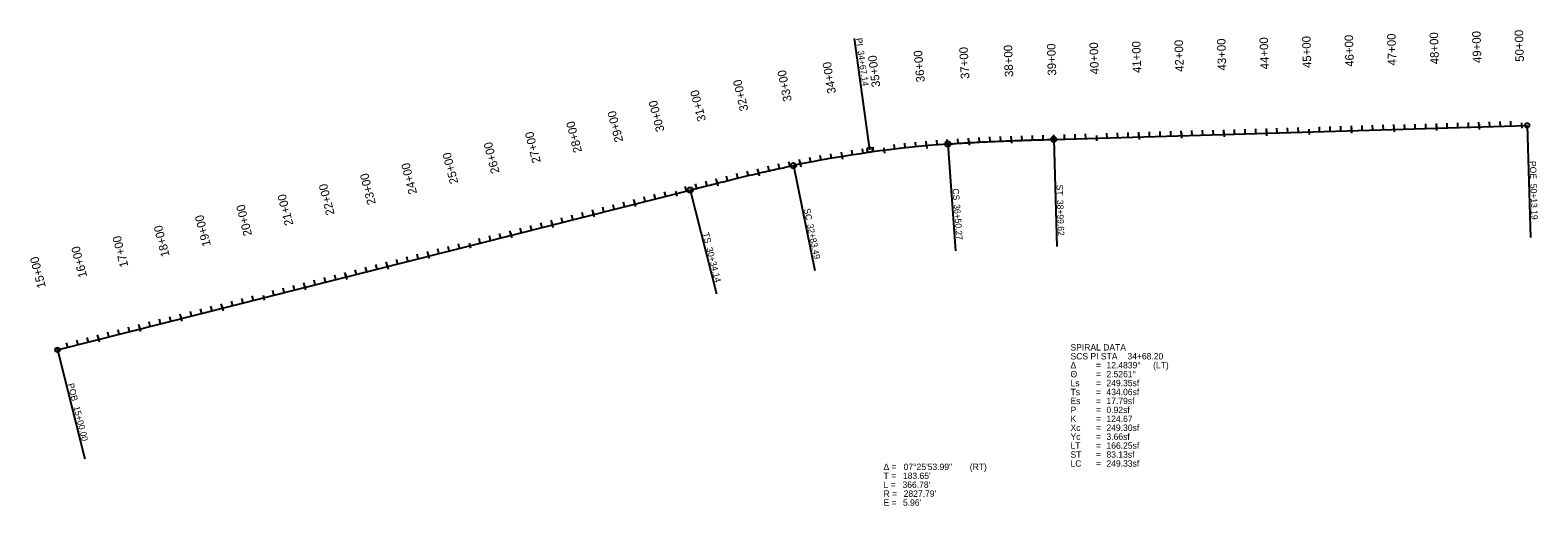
# Model space of a CAD drawing. Extents: x 21446765 to 21450310, y 8416157 to 8417275.
import ezdxf

# ---------------------------------------------------------------- set-up
doc = ezdxf.new("R2010")
doc.units = 0
for name, color, linetype in [('Alignment', 7, 'Continuous'), ('Default', 7, 'Continuous'), ('TextAlignment', 7, 'Continuous'), ('TextAlignmentLrg', 7, 'Continuous'), ('TextAlignmentSml', 7, 'Continuous')]:
    doc.layers.add(name, color=color, linetype=linetype)

msp = doc.modelspace()

# ---------------------------------------------------------------- linework, layer by layer
at = {"layer": 'Alignment'}
for p, q in [((21449171.8, 8417018.5), (21450284.8, 8417051.4)), ((21446829.6, 8416523.7), (21448317.1, 8416899.4))]:
    msp.add_line(p, q, dxfattribs=at)
msp.add_arc((21449130.7, 8414187.4), 2827.8, 94.2179, 101.6496, dxfattribs=at)
for points in [[(21448922.7, 8417007.5), (21448933, 8417008.3), (21448953.8, 8417009.7), (21448995.3, 8417012.1), (21449047.2, 8417014.5), (21449099.1, 8417016.3), (21449140.6, 8417017.6), (21449161.4, 8417018.2), (21449171.8, 8417018.5)], [(21448317.1, 8416899.4), (21448327.1, 8416901.9), (21448347.3, 8416907), (21448387.6, 8416917.2), (21448438, 8416929.6), (21448488.6, 8416941.5), (21448529.2, 8416950.5), (21448549.5, 8416954.8), (21448559.7, 8416956.9)]]:
    msp.add_open_spline(points, degree=3, dxfattribs=at)
at = {"layer": 'Default'}
for p, q in [((21449171.8, 8417018.5), (21450284.8, 8417051.4)), ((21446829.6, 8416523.7), (21448317.1, 8416899.4))]:
    msp.add_line(p, q, dxfattribs=at)
msp.add_arc((21449130.7, 8414187.4), 2827.8, 94.2179, 101.6496, dxfattribs=at)
for points in [[(21448922.7, 8417007.5), (21448933, 8417008.3), (21448953.8, 8417009.7), (21448995.3, 8417012.1), (21449047.2, 8417014.5), (21449099.1, 8417016.3), (21449140.6, 8417017.6), (21449161.4, 8417018.2), (21449171.8, 8417018.5)], [(21448317.1, 8416899.4), (21448327.1, 8416901.9), (21448347.3, 8416907), (21448387.6, 8416917.2), (21448438, 8416929.6), (21448488.6, 8416941.5), (21448529.2, 8416950.5), (21448549.5, 8416954.8), (21448559.7, 8416956.9)]]:
    msp.add_open_spline(points, degree=3, dxfattribs=at)
at = {"layer": 'TextAlignment'}
for p, q in [((21448739.5, 8416994), (21448703.1, 8417255.5)), ((21448703.1, 8417255.5), (21448703.1, 8417255.5)), ((21450284.8, 8417051.4), (21450292.6, 8416787.5)), ((21449171.8, 8417018.5), (21449179.2, 8416766.6)), ((21448922.7, 8417007.5), (21448941.2, 8416756.2)), ((21448922.7, 8417007.5), (21448941.2, 8416756.2)), ((21448559.7, 8416956.9), (21448610.5, 8416710.1)), ((21448559.7, 8416956.9), (21448610.5, 8416710.1)), ((21448317.1, 8416899.4), (21448378.8, 8416655.1)), ((21449179.2, 8416766.6), (21449179.2, 8416766.6)), ((21450292.6, 8416787.5), (21450292.6, 8416787.5)), ((21448941.2, 8416756.2), (21448941.2, 8416756.2)), ((21448941.2, 8416756.2), (21448941.2, 8416756.2)), ((21448610.5, 8416710.1), (21448610.5, 8416710.1)), ((21448610.5, 8416710.1), (21448610.5, 8416710.1)), ((21448378.8, 8416655.1), (21448378.8, 8416655.1)), ((21446829.6, 8416523.7), (21446894.3, 8416267.7)), ((21446894.3, 8416267.7), (21446894.3, 8416267.7))]:
    msp.add_line(p, q, dxfattribs=at)
for centre, radius in [((21450284.8, 8417051.4), 5.34), ((21449171.8, 8417018.5), 6.24), ((21448739.5, 8416994), 6.24), ((21448922.7, 8417007.5), 6.24), ((21448922.7, 8417007.5), 6.24), ((21448559.7, 8416956.9), 6.24), ((21448559.7, 8416956.9), 6.24), ((21448317.1, 8416899.4), 6.24), ((21446829.6, 8416523.7), 5.34)]:
    msp.add_circle(centre, radius, dxfattribs=at)
at = {"layer": 'TextAlignmentLrg'}
for p, q in [((21449871.8, 8417039.2), (21449871.5, 8417050.1)), ((21449971.8, 8417042.1), (21449971.5, 8417053.1)), ((21450071.8, 8417045.1), (21450071.4, 8417056)), ((21450171.7, 8417048), (21450171.4, 8417059)), ((21450271.5, 8417057.1), (21450271.8, 8417044.9)), ((21448972.3, 8417010.7), (21448971.7, 8417021.6)), ((21449072.2, 8417015.3), (21449071.8, 8417026.3)), ((21449172.1, 8417018.5), (21449171.8, 8417029.4)), ((21449271.9, 8417027.6), (21449272.3, 8417015.4)), ((21449372.1, 8417024.4), (21449371.7, 8417035.3)), ((21449472, 8417027.4), (21449471.7, 8417038.3)), ((21449572, 8417030.3), (21449571.6, 8417041.3)), ((21449671.9, 8417033.3), (21449671.6, 8417044.2)), ((21449771.7, 8417042.4), (21449772.1, 8417030.1)), ((21448674.2, 8416978.1), (21448672.5, 8416988.8)), ((21448772.4, 8416998.5), (21448774, 8416986.4)), ((21448872.6, 8417003.3), (21448871.6, 8417014.2)), ((21448478.1, 8416939), (21448475.7, 8416949.6)), ((21448575.8, 8416960.2), (21448573.7, 8416970.9)), ((21448380.9, 8416915.5), (21448378.3, 8416926.1)), ((21448187, 8416866.6), (21448184.3, 8416877.1)), ((21448282.5, 8416897), (21448285.5, 8416885.1)), ((21448090, 8416842.1), (21448087.4, 8416852.6)), ((21447896.1, 8416793.1), (21447893.5, 8416803.7)), ((21447993.1, 8416817.6), (21447990.4, 8416828.2)), ((21447797.7, 8416774.5), (21447800.7, 8416762.7)), ((21447702.2, 8416744.1), (21447699.6, 8416754.7)), ((21447508.3, 8416695.1), (21447505.6, 8416705.7)), ((21447605.3, 8416719.6), (21447602.6, 8416730.2)), ((21447411.4, 8416670.6), (21447408.7, 8416681.2)), ((21447217.5, 8416621.7), (21447214.8, 8416632.2)), ((21447312.9, 8416652.1), (21447315.9, 8416640.2)), ((21447120.5, 8416597.2), (21447117.8, 8416607.8)), ((21446926.6, 8416548.2), (21446923.9, 8416558.8)), ((21447023.5, 8416572.7), (21447020.9, 8416583.3)), ((21446828.1, 8416529.6), (21446831.1, 8416517.8))]:
    msp.add_line(p, q, dxfattribs=at)
at = {"layer": 'TextAlignmentSml'}
for p, q in [((21449896.8, 8417039.9), (21449896.5, 8417050.8)), ((21449921.8, 8417040.7), (21449921.5, 8417051.6)), ((21449946.8, 8417041.4), (21449946.5, 8417052.3)), ((21449996.8, 8417042.9), (21449996.5, 8417053.8)), ((21450021.8, 8417043.6), (21450021.5, 8417054.5)), ((21450046.8, 8417044.4), (21450046.4, 8417055.3)), ((21450071.6, 8417051.2), (21450071.9, 8417039)), ((21450096.7, 8417045.8), (21450096.4, 8417056.8)), ((21450121.7, 8417046.6), (21450121.4, 8417057.5)), ((21450146.7, 8417047.3), (21450146.4, 8417058.2)), ((21450171.5, 8417054.2), (21450171.9, 8417041.9)), ((21450196.7, 8417048.8), (21450196.4, 8417059.7)), ((21450221.7, 8417049.5), (21450221.4, 8417060.4)), ((21450246.7, 8417050.3), (21450246.4, 8417061.2)), ((21450271.5, 8417057.1), (21450271.8, 8417044.9)), ((21448897.5, 8417005.5), (21448896.6, 8417016.4)), ((21448922.4, 8417007.5), (21448921.6, 8417018.4)), ((21448947.3, 8417009.2), (21448946.6, 8417020.1)), ((21448971.9, 8417016.9), (21448972.7, 8417004.6)), ((21448997.3, 8417012.1), (21448996.7, 8417023)), ((21449022.2, 8417013.3), (21449021.7, 8417024.2)), ((21449047.2, 8417014.4), (21449046.8, 8417025.3)), ((21449072, 8417021.5), (21449072.4, 8417009.2)), ((21449097.2, 8417016.2), (21449096.8, 8417027.1)), ((21449122.2, 8417017), (21449121.8, 8417027.9)), ((21449147.2, 8417017.8), (21449146.8, 8417028.7)), ((21449172, 8417024.6), (21449172.3, 8417012.4)), ((21449197.1, 8417019.3), (21449196.8, 8417030.2)), ((21449222.1, 8417020), (21449221.8, 8417030.9)), ((21449247.1, 8417020.7), (21449246.8, 8417031.7)), ((21449271.9, 8417027.6), (21449272.3, 8417015.4)), ((21449297.1, 8417022.2), (21449296.8, 8417033.1)), ((21449322.1, 8417023), (21449321.8, 8417033.9)), ((21449347.1, 8417023.7), (21449346.7, 8417034.6)), ((21449371.9, 8417030.5), (21449372.2, 8417018.3)), ((21449397, 8417025.2), (21449396.7, 8417036.1)), ((21449422, 8417025.9), (21449421.7, 8417036.8)), ((21449447, 8417026.6), (21449446.7, 8417037.6)), ((21449471.8, 8417033.5), (21449472.2, 8417021.3)), ((21449497, 8417028.1), (21449496.7, 8417039)), ((21449522, 8417028.9), (21449521.7, 8417039.8)), ((21449547, 8417029.6), (21449546.7, 8417040.5)), ((21449571.8, 8417036.5), (21449572.1, 8417024.2)), ((21449597, 8417031.1), (21449596.6, 8417042)), ((21449621.9, 8417031.8), (21449621.6, 8417042.7)), ((21449646.9, 8417032.5), (21449646.6, 8417043.5)), ((21449671.7, 8417039.4), (21449672.1, 8417027.2)), ((21449696.9, 8417034), (21449696.6, 8417044.9)), ((21449721.9, 8417034.8), (21449721.6, 8417045.7)), ((21449746.9, 8417035.5), (21449746.6, 8417046.4)), ((21449771.7, 8417042.4), (21449772.1, 8417030.1)), ((21449796.9, 8417037), (21449796.5, 8417047.9)), ((21449821.9, 8417037.7), (21449821.5, 8417048.6)), ((21449846.8, 8417038.5), (21449846.5, 8417049.4)), ((21449871.7, 8417045.3), (21449872, 8417033.1)), ((21449971.6, 8417048.3), (21449972, 8417036)), ((21448625, 8416969.6), (21448623, 8416980.3)), ((21448649.6, 8416973.9), (21448647.7, 8416984.7)), ((21448673.2, 8416984.1), (21448675.2, 8416972)), ((21448698.9, 8416982), (21448697.2, 8416992.8)), ((21448723.6, 8416985.7), (21448722.1, 8416996.5)), ((21448748.4, 8416989.2), (21448746.9, 8417000)), ((21448772.4, 8416998.5), (21448774, 8416986.4)), ((21448798, 8416995.5), (21448796.7, 8417006.4)), ((21448822.8, 8416998.3), (21448821.6, 8417009.2)), ((21448847.7, 8417001), (21448846.6, 8417011.8)), ((21448872, 8417009.4), (21448873.1, 8416997.3)), ((21448453.8, 8416933.3), (21448451.3, 8416943.9)), ((21448476.7, 8416944.9), (21448479.5, 8416933)), ((21448502.5, 8416944.5), (21448500.1, 8416955.2)), ((21448526.9, 8416950), (21448524.6, 8416960.6)), ((21448551.4, 8416955.2), (21448549.1, 8416965.9)), ((21448574.6, 8416966.2), (21448577, 8416954.2)), ((21448600.4, 8416965), (21448598.3, 8416975.7)), ((21448332.4, 8416903.3), (21448329.8, 8416913.9)), ((21448356.7, 8416909.4), (21448354, 8416920)), ((21448379.4, 8416921.4), (21448382.4, 8416909.5)), ((21448405.2, 8416921.5), (21448402.6, 8416932.1)), ((21448429.5, 8416927.4), (21448426.9, 8416938)), ((21448211.2, 8416872.7), (21448208.6, 8416883.3)), ((21448235.5, 8416878.8), (21448232.8, 8416889.4)), ((21448259.7, 8416884.9), (21448257, 8416895.5)), ((21448282.5, 8416897), (21448285.5, 8416885.1)), ((21448308.2, 8416897.2), (21448305.5, 8416907.8)), ((21448041.6, 8416829.8), (21448038.9, 8416840.4)), ((21448065.8, 8416835.9), (21448063.1, 8416846.5)), ((21448088.5, 8416848), (21448091.5, 8416836.1)), ((21448114.3, 8416848.2), (21448111.6, 8416858.8)), ((21448138.5, 8416854.3), (21448135.8, 8416864.9)), ((21448162.8, 8416860.4), (21448160.1, 8416871)), ((21448185.5, 8416872.5), (21448188.5, 8416860.6)), ((21447920.4, 8416799.2), (21447917.7, 8416809.8)), ((21447944.6, 8416805.3), (21447941.9, 8416815.9)), ((21447968.9, 8416811.4), (21447966.2, 8416822)), ((21447991.6, 8416823.5), (21447994.6, 8416811.6)), ((21448017.3, 8416823.7), (21448014.7, 8416834.3)), ((21447750.7, 8416756.3), (21447748, 8416766.9)), ((21447774.9, 8416762.5), (21447772.3, 8416773.1)), ((21447797.7, 8416774.5), (21447800.7, 8416762.7)), ((21447823.4, 8416774.7), (21447820.7, 8416785.3)), ((21447847.7, 8416780.8), (21447845, 8416791.4)), ((21447871.9, 8416787), (21447869.2, 8416797.5)), ((21447894.6, 8416799), (21447897.6, 8416787.1)), ((21447629.5, 8416725.7), (21447626.8, 8416736.3)), ((21447653.7, 8416731.9), (21447651.1, 8416742.4)), ((21447678, 8416738), (21447675.3, 8416748.6)), ((21447700.7, 8416750), (21447703.7, 8416738.2)), ((21447726.5, 8416750.2), (21447723.8, 8416760.8)), ((21447484.1, 8416689), (21447481.4, 8416699.6)), ((21447506.8, 8416701.1), (21447509.8, 8416689.2)), ((21447532.6, 8416701.2), (21447529.9, 8416711.8)), ((21447556.8, 8416707.4), (21447554.1, 8416718)), ((21447581, 8416713.5), (21447578.4, 8416724.1)), ((21447603.8, 8416725.5), (21447606.8, 8416713.7)), ((21447338.6, 8416652.3), (21447336, 8416662.9)), ((21447362.9, 8416658.4), (21447360.2, 8416669)), ((21447387.1, 8416664.5), (21447384.4, 8416675.1)), ((21447409.9, 8416676.6), (21447412.9, 8416664.7)), ((21447435.6, 8416676.8), (21447432.9, 8416687.3)), ((21447459.8, 8416682.9), (21447457.2, 8416693.5)), ((21447193.2, 8416615.5), (21447190.5, 8416626.1)), ((21447216, 8416627.6), (21447219, 8416615.7)), ((21447241.7, 8416627.8), (21447239, 8416638.4)), ((21447265.9, 8416633.9), (21447263.3, 8416644.5)), ((21447290.2, 8416640), (21447287.5, 8416650.6)), ((21447312.9, 8416652.1), (21447315.9, 8416640.2)), ((21447047.8, 8416578.8), (21447045.1, 8416589.4)), ((21447072, 8416584.9), (21447069.3, 8416595.5)), ((21447096.3, 8416591), (21447093.6, 8416601.6)), ((21447119, 8416603.1), (21447122, 8416591.2)), ((21447144.7, 8416603.3), (21447142.1, 8416613.9)), ((21447169, 8416609.4), (21447166.3, 8416620)), ((21446925.1, 8416554.1), (21446928.1, 8416542.3)), ((21446950.8, 8416554.3), (21446948.2, 8416564.9)), ((21446975.1, 8416560.4), (21446972.4, 8416571)), ((21446999.3, 8416566.6), (21446996.6, 8416577.1)), ((21447022, 8416578.6), (21447025, 8416566.7)), ((21446828.1, 8416529.6), (21446831.1, 8416517.8)), ((21446853.9, 8416529.8), (21446851.2, 8416540.4)), ((21446878.1, 8416535.9), (21446875.4, 8416546.5)), ((21446902.3, 8416542.1), (21446899.7, 8416552.7))]:
    msp.add_line(p, q, dxfattribs=at)

# ---------------------------------------------------------------- texts
at = {"layer": 'TextAlignment'}
for s, rotation, p in [('PI ', 277.9337, (21448706.4, 8417255.9)), ('34+67.14', 277.9337, (21448710.5, 8417226.3)), ('POE ', 271.6918, (21450290.6, 8416967.5)), ('ST', 271.6918, (21449178.2, 8416911.9)), ('50+13.19', 271.6918, (21450292.2, 8416913.7)), ('CS', 274.2179, (21448933.7, 8416902.5)), ('CS', 274.2179, (21448933.7, 8416902.5)), ('38+99.62', 271.6918, (21449179.3, 8416875.9)), ('SC', 281.6496, (21448584.1, 8416854.5)), ('SC', 281.6496, (21448584.1, 8416854.5)), ('36+50.27', 274.2179, (21448936.5, 8416865.5)), ('36+50.27', 274.2179, (21448936.5, 8416865.5)), ('32+83.49', 281.6496, (21448591.6, 8416818.2)), ('32+83.49', 281.6496, (21448591.6, 8416818.2)), ('TS', 284.1757, (21448346.2, 8416797.5)), ('30+34.14', 284.1757, (21448355, 8416762.6)), ('POB ', 284.1757, (21446853.4, 8416443.1)), ('15+00.00', 284.1757, (21446867, 8416389.3))]:
    msp.add_text(s, height=15, rotation=rotation, dxfattribs=at).set_placement(p)
for s, p in [('SPIRAL DATA', (21449211.2, 8416522.1)), ('Δ', (21449211.2, 8416480.1)), ('SCS PI STA ', (21449211.2, 8416501.1)), ('= ', (21449271.2, 8416480.1)), ('12.4839°', (21449295.7, 8416480.1)), ('34+68.20', (21449345, 8416501.1)), (' (LT)', (21449399.7, 8416480.1)), ('Θ ', (21449211.2, 8416459.1)), ('Ls', (21449211.2, 8416438.1)), ('= ', (21449271.2, 8416459.1)), ('= ', (21449271.2, 8416438.1)), ('2.5261°', (21449295.7, 8416459.1)), ('249.35sf', (21449295.7, 8416438.1)), ('Ts', (21449211.2, 8416417.1)), ('= ', (21449271.2, 8416417.1)), ('434.06sf', (21449295.7, 8416417.1)), ('Es', (21449211.2, 8416396.1)), ('P', (21449211.2, 8416375.1)), ('= ', (21449271.2, 8416396.1)), ('= ', (21449271.2, 8416375.1)), ('0.92sf', (21449295.7, 8416375.1)), ('17.79sf', (21449295.7, 8416396.1)), ('Xc', (21449211.2, 8416333.1)), ('K', (21449211.2, 8416354.1)), ('= ', (21449271.2, 8416354.1)), ('= ', (21449271.2, 8416333.1)), ('249.30sf', (21449295.7, 8416333.1)), ('124.67', (21449295.7, 8416354.1)), ('Yc', (21449211.2, 8416312.1)), ('LT', (21449211.2, 8416291.1)), ('= ', (21449271.2, 8416312.1)), ('3.66sf', (21449295.7, 8416312.1)), ('166.25sf', (21449295.7, 8416291.1)), ('ST ', (21449211.2, 8416270.1)), ('= ', (21449271.2, 8416291.1)), ('= ', (21449271.2, 8416270.1)), ('83.13sf', (21449295.7, 8416270.1)), ('T = ', (21448771.6, 8416220.1)), ('Δ = ', (21448771.6, 8416241.1)), ("183.65'", (21448817.2, 8416220.1)), ('07°25\'53.99"', (21448819, 8416241.1)), (' (RT)', (21448968.8, 8416241.1)), ('LC', (21449211.2, 8416249.1)), ('= ', (21449271.2, 8416249.1)), ('249.33sf', (21449295.7, 8416249.1)), ('L = ', (21448771.6, 8416199.1)), ("366.78'", (21448816.2, 8416199.1)), ('R = ', (21448771.6, 8416178.1)), ('E = ', (21448771.6, 8416157.1)), ("5.96'", (21448817.2, 8416157.1)), ("2827.79'", (21448819, 8416178.1))]:
    msp.add_text(s, height=15, dxfattribs=at).set_placement(p)
at = {"layer": 'TextAlignmentLrg'}
for s, rotation, p in [('50+00', 91.6918, (21450277.3, 8417201.2)), ('40+00', 91.6918, (21449277.7, 8417171.7)), ('45+00', 91.6918, (21449777.5, 8417186.5)), ('35+00', 97.2627, (21448764.2, 8417142.5)), ('30+00', 104.1757, (21448256.9, 8417038.9)), ('25+00', 104.1757, (21447772.2, 8416916.5)), ('20+00', 104.1757, (21447287.4, 8416794)), ('15+00', 104.1757, (21446802.6, 8416671.6))]:
    msp.add_text(s, height=20.04, rotation=rotation, dxfattribs=at).set_placement(p)
at = {"layer": 'TextAlignmentSml'}
for s, rotation, p in [('46+00', 91.6918, (21449877.4, 8417189.4)), ('47+00', 91.6918, (21449977.4, 8417192.4)), ('48+00', 91.6918, (21450077.3, 8417195.3)), ('49+00', 91.6918, (21450177.3, 8417198.3)), ('50+00', 91.6918, (21450277.3, 8417201.2)), ('37+00', 93.3108, (21448973.6, 8417161.1)), ('38+00', 92.095, (21449076.7, 8417165.6)), ('39+00', 91.6918, (21449177.7, 8417168.8)), ('40+00', 91.6918, (21449277.7, 8417171.7)), ('41+00', 91.6918, (21449377.6, 8417174.7)), ('42+00', 91.6918, (21449477.6, 8417177.6)), ('43+00', 91.6918, (21449577.6, 8417180.6)), ('44+00', 91.6918, (21449677.5, 8417183.5)), ('45+00', 91.6918, (21449777.5, 8417186.5)), ('34+00', 99.2889, (21448659.9, 8417127.7)), ('35+00', 97.2627, (21448764.2, 8417142.5)), ('36+00', 95.2365, (21448868.9, 8417153.6)), ('32+00', 103.058, (21448454, 8417087.4)), ('33+00', 101.315, (21448556.2, 8417109.2)), ('31+00', 103.9995, (21448354.4, 8417063.4)), ('30+00', 104.1757, (21448256.9, 8417038.9)), ('28+00', 104.1757, (21448063, 8416989.9)), ('29+00', 104.1757, (21448160, 8417014.4)), ('27+00', 104.1757, (21447966.1, 8416965.5)), ('25+00', 104.1757, (21447772.2, 8416916.5)), ('26+00', 104.1757, (21447869.1, 8416941)), ('24+00', 104.1757, (21447675.2, 8416892)), ('22+00', 104.1757, (21447481.3, 8416843)), ('23+00', 104.1757, (21447578.3, 8416867.5)), ('21+00', 104.1757, (21447384.3, 8416818.5)), ('19+00', 104.1757, (21447190.4, 8416769.5)), ('20+00', 104.1757, (21447287.4, 8416794)), ('18+00', 104.1757, (21447093.5, 8416745.1)), ('16+00', 104.1757, (21446899.6, 8416696.1)), ('17+00', 104.1757, (21446996.5, 8416720.6)), ('15+00', 104.1757, (21446802.6, 8416671.6))]:
    msp.add_text(s, height=20.04, rotation=rotation, dxfattribs=at).set_placement(p)

doc.saveas('drawing.dxf')
